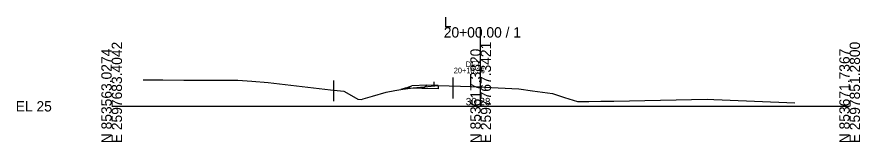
# Model space of a CAD drawing. Extents: x -26 to 1203, y -10 to 9526.
# Drawn here: x 974.3 to 1202.8, y -9.7 to 24.2 of the extents above; entities that cross this region are included whole.
import ezdxf

# ---------------------------------------------------------------- set-up
doc = ezdxf.new("R2010")
doc.units = 0
for name, color, linetype in [('Exist Cross Section Cell', 7, 'Continuous'), ('Exist XS Center Line Elevation Label', 7, 'Continuous'), ('Exist XS Ground Line', 7, 'Continuous'), ('Prop XS Alignment Label', 7, 'Continuous'), ('Prop XS Earthwork Shape', 7, 'Continuous'), ('Prop XS EOT Tick Mark', 7, 'Continuous'), ('Prop XS Exc Vertical Line 1', 7, 'Continuous'), ('Prop XS Exc Vertical Line 2', 7, 'Continuous'), ('Prop XS Finish Grade', 7, 'Continuous'), ('Prop XS Finish Grade Earthwork', 7, 'Continuous'), ('Prop XS Finish Grade Paved Shoulder', 7, 'Continuous'), ('Prop XS Pvmt Edge Slope', 7, 'Continuous'), ('Prop XS Side Slope Text', 7, 'Continuous'), ('Prop XS Station Labels', 7, 'Continuous'), ('Prop XS Subgrade Earthwork', 7, 'Continuous')]:
    doc.layers.add(name, color=color, linetype=linetype)

msp = doc.modelspace()

# ---------------------------------------------------------------- linework, layer by layer
at = {"layer": 'Exist Cross Section Cell'}
for p, q in [((1100, 0), (1100, 21.42)), ((1000, 0), (1100, 0)), ((1100, 0), (1200, 0))]:
    msp.add_line(p, q, dxfattribs=at)
at = {"layer": 'Exist XS Ground Line'}
for p, q in [((1008.51, 7.13), (1013.87, 7.14)), ((1013.87, 7.14), (1019.53, 7.12)), ((1019.53, 7.12), (1023.35, 7.05)), ((1023.35, 7.05), (1034.23, 7.11)), ((1034.23, 7.11), (1038.01, 6.8)), ((1038.01, 6.8), (1042.4, 6.49)), ((1042.4, 6.49), (1056.25, 4.82)), ((1056.25, 4.82), (1059.28, 4.47)), ((1076.7, 4.27), (1078.9, 4.64)), ((1078.9, 4.64), (1081.75, 5.03)), ((1081.75, 5.03), (1085.66, 5.41)), ((1085.66, 5.41), (1088.45, 5.61)), ((1088.45, 5.61), (1097.55, 5.36)), ((1097.55, 5.36), (1099.51, 5.31)), ((1099.51, 5.31), (1100, 5.28)), ((1100, 5.28), (1101, 5.23)), ((1101, 5.23), (1110.3, 4.76)), ((1110.3, 4.76), (1114.04, 4.22)), ((1059.28, 4.47), (1062.93, 4.11)), ((1062.93, 4.11), (1063.75, 3.65)), ((1063.75, 3.65), (1066.71, 1.97)), ((1068.16, 2.03), (1070.66, 2.76)), ((1070.66, 2.76), (1074.35, 3.8)), ((1074.35, 3.8), (1076.7, 4.27)), ((1114.04, 4.22), (1119.45, 3.47)), ((1119.45, 3.47), (1122.74, 2.38)), ((1122.74, 2.38), (1126.26, 1.27)), ((1066.71, 1.97), (1067.75, 1.81)), ((1067.75, 1.81), (1068.16, 2.03)), ((1126.26, 1.27), (1129.32, 1.27)), ((1129.32, 1.27), (1132.53, 1.41)), ((1132.53, 1.41), (1135.62, 1.37)), ((1135.62, 1.37), (1136.08, 1.4)), ((1136.08, 1.4), (1161.39, 1.91)), ((1161.39, 1.91), (1163.21, 1.82)), ((1163.21, 1.82), (1165.46, 1.78)), ((1165.46, 1.78), (1185.13, 0.99))]:
    msp.add_line(p, q, dxfattribs=at)
at = {"layer": 'Prop XS Earthwork Shape'}
for points in [[(1079.55, 4.95), (1078.35, 4.55), (1078.9, 4.64), (1080.88, 4.91)], [(1085.66, 5.41), (1088.45, 5.61), (1088.45, 4.71), (1080.88, 4.91), (1081.75, 5.03)]]:
    msp.add_lwpolyline(points, close=True, dxfattribs=at)
at = {"layer": 'Prop XS EOT Tick Mark'}
msp.add_line((1087.38, 5.63), (1087.38, 6.63), dxfattribs=at)
at = {"layer": 'Prop XS Exc Vertical Line 1'}
msp.add_line((1060.08, 7), (1060.08, 1.42), dxfattribs=at)
at = {"layer": 'Prop XS Exc Vertical Line 2'}
msp.add_line((1092.42, 7.76), (1092.42, 2.13), dxfattribs=at)
at = {"layer": 'Prop XS Finish Grade'}
for p in [(1079.55, 4.95), (1085.38, 5.69)]:
    msp.add_line(p, (1081.38, 5.56), dxfattribs=at)
at = {"layer": 'Prop XS Finish Grade Earthwork'}
msp.add_line((1079.55, 4.95), (1078.35, 4.55), dxfattribs=at)
at = {"layer": 'Prop XS Finish Grade Paved Shoulder'}
for p, q in [((1087.38, 5.63), (1085.38, 5.69)), ((1088.45, 5.61), (1087.38, 5.63))]:
    msp.add_line(p, q, dxfattribs=at)
at = {"layer": 'Prop XS Pvmt Edge Slope'}
msp.add_line((1085.38, 5.69), (1084.51, 4.81), dxfattribs=at)
at = {"layer": 'Prop XS Side Slope Text'}
msp.add_line((1097.37, 5.22), (1097.37, 8.74), dxfattribs=at)
at = {"layer": 'Prop XS Subgrade Earthwork'}
for points in [[(1088.45, 4.71), (1079.55, 4.95)], [(1088.45, 5.61), (1088.45, 4.71)]]:
    msp.add_lwpolyline(points, dxfattribs=at)

# ---------------------------------------------------------------- texts
at = {"layer": 'Exist Cross Section Cell'}
for s, p in [('L', (1090, 21.42)), ('20+00.00 / 1', (1090, 18.62)), ('EL 25', (974, -1.4))]:
    msp.add_text(s, height=2.8, dxfattribs=at).set_placement(p)
for s, p in [('E 2597683.4042', (1002.8, -10)), ('E 2597767.3421', (1102.8, -10)), ('E 2597851.2800', (1202.8, -10)), ('N 853563.0274', (1000, -10)), ('N 853617.3820', (1100, -10)), ('N 853671.7367', (1200, -10))]:
    msp.add_text(s, height=2.8, rotation=90, dxfattribs=at).set_placement(p)
at = {"layer": 'Exist XS Center Line Elevation Label'}
msp.add_text('30.28', height=2, dxfattribs=at).set_placement((1095.96, 0.28))
at = {"layer": 'Prop XS Alignment Label'}
msp.add_text('DET', height=1.5, dxfattribs=at).set_placement((1095.97, 10.65))
at = {"layer": 'Prop XS Station Labels'}
msp.add_text('20+10.36', height=1.5, dxfattribs=at).set_placement((1092.71, 8.96))

doc.saveas('drawing.dxf')
